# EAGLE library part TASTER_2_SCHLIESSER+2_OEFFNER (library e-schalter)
Taster, 2 Schließer, 2 Öffner
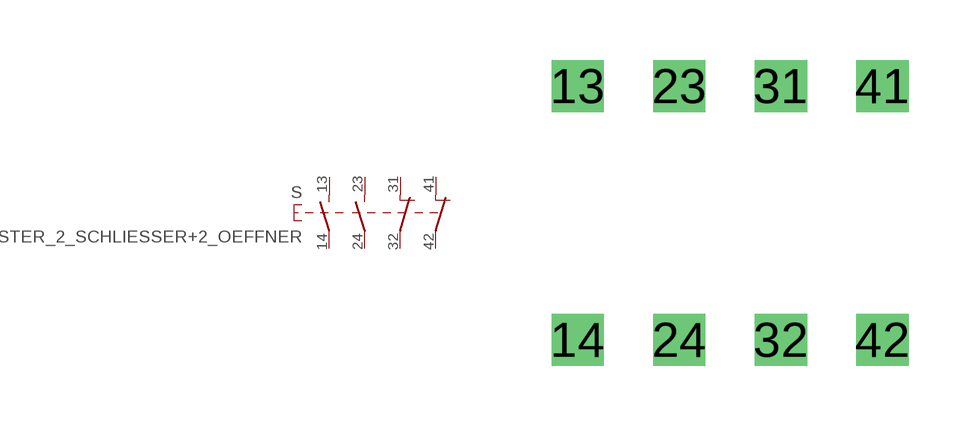
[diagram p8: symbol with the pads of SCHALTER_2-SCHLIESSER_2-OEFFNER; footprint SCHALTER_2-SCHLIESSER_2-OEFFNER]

Designator prefix S

## TASTER_2_SCHLIESSER+2_OEFFNER  [SCHALTER_2-SCHLIESSER_2-OEFFNER]
13  13  pas
14  14  pas
23  23  pas
24  24  pas
31  31  pas
32  32  pas
41  41  pas
42  42  pas

## Footprint SCHALTER_2-SCHLIESSER_2-OEFFNER (pad centres in mm)
Dummy
drill 0.8 square: 13 -3.81,3.175; 14 -3.81,-3.175; 23 -1.27,3.175; 24 -1.27,-3.175; 31 1.27,3.175; 32 1.27,-3.175; 41 3.81,3.175; 42 3.81,-3.175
